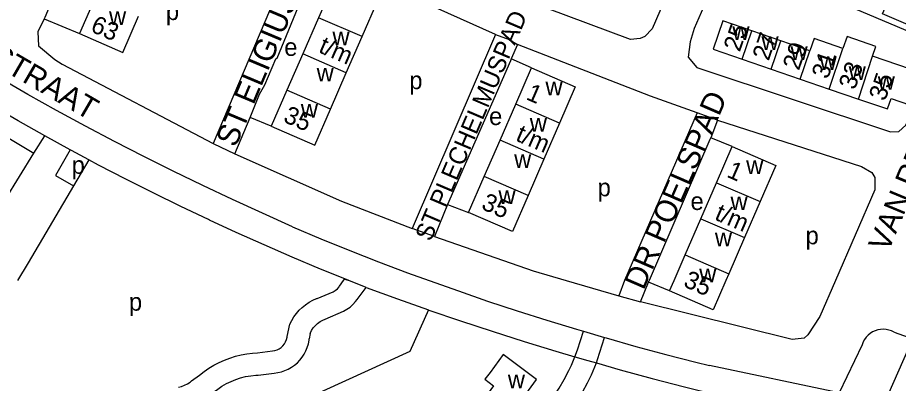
# Model space of a CAD drawing. Extents: x 162804 to 165059, y 381530 to 382901.
# Drawn here: x 163445.8 to 163644.1, y 381726.8 to 381809.3 of the extents above; entities that cross this region are included whole.
import ezdxf

# ---------------------------------------------------------------- set-up
doc = ezdxf.new("R2010")
doc.units = 0
for name, color, linetype in [('BLT_Basislijn', 7, 'Continuous'), ('BLT_Bebouwing', 7, 'Continuous'), ('BLT_Centroide', 7, 'Continuous'), ('BLT_Huisnummer', 7, 'Continuous'), ('BLT_Huisnummer_ tussenligend', 7, 'Continuous'), ('BLT_Huisnummer_reeks', 7, 'Continuous'), ('BLT_Onderverdeling_panden', 7, 'Continuous'), ('BLT_Straatnaam', 7, 'Continuous'), ('BLT_Straatnaam_verkleind', 7, 'Continuous')]:
    doc.layers.add(name, color=color, linetype=linetype)

msp = doc.modelspace()

# ---------------------------------------------------------------- linework, layer by layer
at = {"layer": 'BLT_Basislijn'}
for p, q in [((163508.81, 381825.69), (163489.79, 381780.91)), ((163553.38, 381805.49), (163514.14, 381823.1)), ((163653.55, 381803.05), (163629.47, 381813.33)), ((163451.76, 381809.01), (163459.7, 381805.68)), ((163553.38, 381805.49), (163534.59, 381761.76)), ((163558.32, 381803.23), (163556.95, 381800.02)), ((163561.46, 381797.95), (163556.95, 381800.02)), ((163494.7, 381778.56), (163498.12, 381786.73)), ((163502.88, 381784.79), (163498.12, 381786.73)), ((163598.78, 381787.81), (163582.41, 381750)), ((163603.38, 381786.16), (163598.78, 381787.81)), ((163603.38, 381786.16), (163601.85, 381782.2)), ((163449.46, 381778.72), (163451.88, 381782.63)), ((163457.64, 381779.46), (163451.88, 381782.63)), ((163489.79, 381780.91), (163494.7, 381778.56)), ((163606.68, 381780.21), (163601.85, 381782.2)), ((163461.83, 381777.22), (163458.38, 381771.38)), ((163458.38, 381771.38), (163448.14, 381754)), ((163542.58, 381767.18), (163539.63, 381759.95)), ((163542.58, 381767.18), (163547.34, 381765.32)), ((163539.63, 381759.95), (163534.59, 381761.76)), ((163448.14, 381754), (163445.78, 381750)), ((163518.26, 381748.73), (163519.19, 381750)), ((163519.19, 381750), (163519.4, 381750.29)), ((163519.4, 381750.29), (163520.19, 381750.08)), ((163520.37, 381750), (163520.19, 381750.08)), ((163524.27, 381748.46), (163520.37, 381750)), ((163569.3, 381750), (163581.13, 381746.53)), ((163582.41, 381750), (163581.13, 381746.53)), ((163586.04, 381745.22), (163587.85, 381749.62)), ((163587.85, 381749.62), (163588.01, 381750)), ((163592.58, 381747.66), (163587.85, 381749.62)), ((163513.21, 381746), (163516.81, 381747.48)), ((163522.25, 381745.71), (163524.27, 381748.46)), ((163581.13, 381746.53), (163586.04, 381745.22)), ((163515.04, 381741.34), (163519.18, 381743.08)), ((163506.48, 381737.41), (163507.08, 381740.19)), ((163511.62, 381738.11), (163511.45, 381736.89)), ((163573.17, 381738.57), (163577.92, 381737.18)), ((163643.14, 381738.37), (163647.37, 381736.86)), ((163638.42, 381716.6), (163647.37, 381736.86)), ((163499.77, 381733.71), (163503.15, 381734.15)), ((163570.52, 381730.95), (163571.26, 381732.83)), ((163575.02, 381728.75), (163576.09, 381731.43)), ((163499.97, 381728.71), (163503.55, 381729.17)), ((163484.97, 381727.38), (163486.71, 381728.67))]:
    msp.add_line(p, q, dxfattribs=at)
for points in [[(163597.55, 381827.29), (163588.69, 381806.75), (163587.02, 381805), (163585.93, 381804.58), (163583.75, 381804.36), (163564.87, 381811.42), (163541.46, 381821.29), (163539.68, 381823.17), (163539.55, 381824.83), (163549.28, 381848.27)], [(163465.65, 381841.88), (163451.89, 381809.28), (163451.76, 381809.01)], [(163605.48, 381823.75), (163598.15, 381806.85), (163597.24, 381803.85), (163596.76, 381800.38), (163598.72, 381798.05), (163642.29, 381783.55), (163644.18, 381783.63), (163645.81, 381785.02), (163653.55, 381803.05)], [(163498.12, 381786.73), (163500.21, 381791.99), (163501.43, 381794.13), (163503.96, 381800.02), (163504.25, 381800.16), (163512.11, 381819.35), (163512.27, 381819.65)], [(163507.64, 381762.13), (163500.89, 381765.16), (163494.16, 381768.26), (163487.47, 381771.43), (163480.82, 381774.68), (163474.2, 381777.99), (163467.62, 381781.38), (163461.07, 381784.84), (163454.57, 381788.37), (163448.1, 381791.97), (163441.67, 381795.64), (163435.28, 381799.37), (163428.93, 381803.18), (163422.62, 381807.06), (163418.08, 381809.9)], [(163451.76, 381809.01), (163450.36, 381806.05), (163450.49, 381802.91), (163454.18, 381799.86), (163455.82, 381798.75), (163489.79, 381780.91)], [(163553.38, 381805.49), (163556.45, 381804.34), (163558.32, 381803.23)], [(163598.78, 381787.81), (163588.32, 381791.54), (163558.32, 381803.23)], [(163556.95, 381800.02), (163556.73, 381799.52), (163542.58, 381767.18)], [(163436.05, 381791.78), (163433.78, 381788.09), (163449.46, 381778.72)], [(163451.88, 381782.63), (163445.87, 381786.02), (163439.9, 381789.49), (163436.05, 381791.78)], [(163603.38, 381786.16), (163635.76, 381775.75), (163638.15, 381774.36), (163638.79, 381773.24), (163638.82, 381770.47), (163629.96, 381750)], [(163588.01, 381750), (163588.05, 381750.11), (163601.73, 381781.89), (163601.85, 381782.2)], [(163439.13, 381770.55), (163442.96, 381768.22), (163449.46, 381778.72)], [(163457.64, 381779.46), (163454.34, 381773.65), (163458.38, 381771.38)], [(163461.83, 381777.22), (163457.93, 381779.3), (163457.64, 381779.46)], [(163489.01, 381763.62), (163488.73, 381763.75), (163482.5, 381766.72), (163476.3, 381769.76), (163470.14, 381772.87), (163464.02, 381776.05), (163461.83, 381777.22)], [(163494.7, 381778.56), (163518.73, 381767.87), (163534.59, 381761.76)], [(163520.19, 381750.08), (163513.98, 381752.6), (163507.62, 381755.28), (163501.29, 381758.03), (163494.99, 381760.85), (163489.01, 381763.62)], [(163507.64, 381762.13), (163514.08, 381759.43), (163520.56, 381756.81), (163527.06, 381754.26), (163533.59, 381751.78), (163538.44, 381750)], [(163539.63, 381759.95), (163561.84, 381752.19), (163569.3, 381750)], [(163538.44, 381750), (163545.02, 381747.66), (163551.62, 381745.39), (163558.26, 381743.19), (163564.91, 381741.08), (163571.59, 381739.04), (163573.17, 381738.57)], [(163629.96, 381750), (163626.43, 381741.93), (163623.72, 381737.77), (163622.86, 381737.06), (163620.22, 381736.76), (163586.04, 381745.22)], [(163516.81, 381747.48), (163517.32, 381747.8), (163517.78, 381748.18), (163518.18, 381748.62), (163518.26, 381748.73)], [(163524.27, 381748.46), (163531.32, 381745.87), (163538.27, 381743.42)], [(163507.08, 381740.19), (163507.51, 381741.04), (163508.01, 381741.84), (163508.58, 381742.61), (163509.21, 381743.32), (163509.89, 381743.97), (163510.63, 381744.57), (163511.42, 381745.1), (163512.25, 381745.56), (163513.11, 381745.96), (163513.21, 381746)], [(163519.18, 381743.08), (163519.93, 381743.53), (163520.63, 381744.04), (163521.28, 381744.62), (163521.88, 381745.25), (163522.25, 381745.71)], [(163538.27, 381743.42), (163534.12, 381734.01), (163500, 381718.5), (163478.02, 381708.51), (163453.55, 381693.34), (163440.16, 381684.96)], [(163538.27, 381743.42), (163538.4, 381743.37), (163545.51, 381740.93), (163552.65, 381738.58), (163559.81, 381736.3), (163566.99, 381734.1), (163571.26, 381732.83)], [(163511.62, 381738.11), (163511.96, 381738.74), (163512.35, 381739.32), (163512.82, 381739.86), (163513.34, 381740.34), (163513.91, 381740.76), (163514.52, 381741.11), (163515.04, 381741.34)], [(163643.14, 381738.37), (163642.57, 381738.65), (163641.97, 381738.85), (163641.35, 381738.98), (163640.72, 381739.02), (163640.09, 381738.99), (163639.47, 381738.88), (163638.87, 381738.69), (163638.29, 381738.42), (163637.76, 381738.09), (163637.27, 381737.68), (163636.84, 381737.23), (163636.46, 381736.72), (163636.16, 381736.16), (163635.91, 381735.54)], [(163503.15, 381734.15), (163503.68, 381734.24), (163504.2, 381734.4), (163504.68, 381734.63), (163505.13, 381734.94), (163505.52, 381735.3), (163505.86, 381735.73), (163506.13, 381736.19), (163506.33, 381736.69), (163506.45, 381737.22), (163506.48, 381737.41)], [(163571.26, 381732.83), (163571.87, 381734.37), (163573.17, 381738.57)], [(163576.09, 381731.43), (163576.38, 381732.18), (163577.92, 381737.18)], [(163577.92, 381737.18), (163578.29, 381737.07), (163585.02, 381735.18), (163591.76, 381733.37), (163598.53, 381731.64), (163601.59, 381730.89)], [(163503.55, 381729.17), (163504.38, 381729.28), (163505.18, 381729.46), (163505.97, 381729.72), (163506.73, 381730.06), (163507.46, 381730.47), (163508.14, 381730.95), (163508.77, 381731.48), (163509.35, 381732.08), (163509.87, 381732.73), (163510.32, 381733.43), (163510.7, 381734.17), (163511.01, 381734.94), (163511.25, 381735.73), (163511.41, 381736.55), (163511.45, 381736.89)], [(163635.91, 381735.54), (163630.75, 381724.69), (163601.59, 381730.89)], [(163486.71, 381728.67), (163487.75, 381729.49), (163488.83, 381730.24), (163489.96, 381730.92), (163491.13, 381731.53), (163492.33, 381732.07), (163493.56, 381732.54), (163494.82, 381732.93), (163496.1, 381733.25), (163497.39, 381733.48), (163498.7, 381733.64), (163499.77, 381733.71)], [(163571.26, 381732.83), (163574.19, 381731.97), (163576.09, 381731.43)], [(163576.09, 381731.43), (163581.42, 381729.92), (163588.67, 381727.95), (163595.94, 381726.05), (163603.23, 381724.23), (163604.56, 381723.92)], [(163562.45, 381718.4), (163563.86, 381720.17), (163565.2, 381721.99), (163566.48, 381723.86), (163567.69, 381725.77), (163568.83, 381727.72), (163569.9, 381729.71), (163570.52, 381730.95)], [(163481.99, 381725.98), (163482.69, 381726.16), (163483.37, 381726.4), (163484.01, 381726.72), (163484.62, 381727.11), (163484.97, 381727.38)], [(163489.92, 381724.84), (163490.83, 381725.55), (163491.79, 381726.19), (163492.79, 381726.77), (163493.83, 381727.28), (163494.9, 381727.71), (163496, 381728.07), (163497.12, 381728.35), (163498.26, 381728.56), (163499.41, 381728.68), (163499.97, 381728.71)], [(163566.31, 381715.22), (163567.77, 381717.06), (163569.17, 381718.95), (163570.5, 381720.88), (163571.77, 381722.86), (163572.96, 381724.88), (163574.09, 381726.93), (163575.02, 381728.75)]]:
    msp.add_lwpolyline(points, dxfattribs=at)
at = {"layer": 'BLT_Bebouwing'}
for p, q in [((163517.11, 381817.41), (163513.55, 381809.26)), ((163463.24, 381813.84), (163459.7, 381805.68)), ((163513.55, 381809.26), (163509.99, 381801.1)), ((163519.79, 381796.83), (163523.35, 381804.99)), ((163617.64, 381804.05), (163611.09, 381806.29)), ((163624.18, 381801.8), (163617.64, 381804.05)), ((163509.99, 381801.1), (163506.43, 381792.95)), ((163608.9, 381799.9), (163615.45, 381797.66)), ((163516.23, 381788.67), (163519.79, 381796.83)), ((163557.93, 381789.8), (163561.46, 381797.95)), ((163615.45, 381797.66), (163622, 381795.42)), ((163622, 381795.42), (163628.54, 381793.17)), ((163506.43, 381792.95), (163502.88, 381784.79)), ((163628.54, 381793.17), (163635.09, 381790.93)), ((163554.4, 381781.64), (163557.93, 381789.8)), ((163567.82, 381785.52), (163564.29, 381777.36)), ((163550.87, 381773.48), (163554.4, 381781.64)), ((163603.16, 381772.06), (163606.68, 381780.21)), ((163564.29, 381777.36), (163560.76, 381769.2)), ((163547.34, 381765.32), (163550.87, 381773.48)), ((163599.63, 381763.93), (163603.16, 381772.06)), ((163612.98, 381767.82), (163609.46, 381759.68)), ((163596.11, 381755.79), (163599.63, 381763.93)), ((163609.46, 381759.68), (163605.93, 381751.54)), ((163593.61, 381750), (163596.11, 381755.79)), ((163605.93, 381751.54), (163605.27, 381750)), ((163592.58, 381747.66), (163593.61, 381750))]:
    msp.add_line(p, q, dxfattribs=at)
for points in [[(163523.35, 381804.99), (163526.9, 381813.14), (163517.11, 381817.41)], [(163652.76, 381813.71), (163650.3, 381808.02), (163649.45, 381806.26), (163640.52, 381810.11), (163643.79, 381817.7), (163646.09, 381816.71)], [(163459.7, 381805.68), (163469.48, 381801.43), (163473.02, 381809.59)], [(163611.09, 381806.29), (163604.55, 381808.54), (163602.36, 381802.15), (163608.9, 381799.9)], [(163631.63, 381802.35), (163625.16, 381804.57), (163624.18, 381801.8)], [(163638.29, 381800.6), (163639.04, 381802.77), (163632.54, 381805.01), (163631.63, 381802.35)], [(163635.09, 381790.93), (163641.64, 381788.69), (163642.45, 381791.06), (163646.63, 381789.62), (163649.68, 381796.66), (163638.29, 381800.6)], [(163561.46, 381797.95), (163571.35, 381793.67), (163567.82, 381785.52)], [(163502.88, 381784.79), (163512.67, 381780.52), (163516.23, 381788.67)], [(163606.68, 381780.21), (163616.5, 381775.95), (163612.98, 381767.82)], [(163560.76, 381769.2), (163557.23, 381761.04), (163547.34, 381765.32)], [(163605.27, 381750), (163602.43, 381743.4), (163592.58, 381747.66)], [(163557.79, 381721.13), (163562.64, 381727.71), (163555.14, 381733.31), (163552.15, 381729.31), (163550.98, 381727.75), (163552.97, 381726.26), (163549.68, 381721.86), (163551.23, 381720.7), (163555.23, 381717.7), (163557.79, 381721.13)]]:
    msp.add_lwpolyline(points, dxfattribs=at)
at = {"layer": 'BLT_Onderverdeling_panden'}
for p, q in [((163523.35, 381804.99), (163513.55, 381809.26)), ((163608.9, 381799.9), (163611.09, 381806.29)), ((163615.45, 381797.66), (163617.64, 381804.05)), ((163519.79, 381796.83), (163509.99, 381801.1)), ((163622, 381795.42), (163624.18, 381801.8)), ((163628.54, 381793.17), (163631.63, 381802.35)), ((163635.09, 381790.93), (163638.29, 381800.6)), ((163516.23, 381788.67), (163506.43, 381792.95)), ((163567.82, 381785.52), (163557.93, 381789.8)), ((163564.29, 381777.36), (163554.4, 381781.64)), ((163560.76, 381769.2), (163550.87, 381773.48)), ((163603.16, 381772.06), (163612.98, 381767.82)), ((163599.63, 381763.93), (163609.46, 381759.68)), ((163596.11, 381755.79), (163605.93, 381751.54))]:
    msp.add_line(p, q, dxfattribs=at)

# ---------------------------------------------------------------- texts
at = {"layer": 'BLT_Centroide'}
for s, p in [('w', (163466.36, 381807.62)), ('p', (163479.17, 381808.73)), ('w', (163606.72, 381804.22)), ('w', (163516.67, 381803.03)), ('w', (163613.27, 381801.97)), ('e', (163505.82, 381800.64)), ('w', (163619.81, 381799.72)), ('w', (163626.36, 381797.5)), ('w', (163513.11, 381794.88)), ('w', (163632.91, 381795.25)), ('p', (163533.97, 381793.15)), ('w', (163564.64, 381791.75)), ('w', (163639.45, 381793)), ('w', (163509.55, 381786.72)), ('e', (163551.94, 381785.06)), ('w', (163561.11, 381783.56)), ('p', (163457.95, 381774.05)), ('w', (163557.58, 381775.41)), ('w', (163609.83, 381774)), ('p', (163576.37, 381769)), ('w', (163554.05, 381767.25)), ('e', (163597.3, 381765.91)), ('w', (163606.3, 381765.88)), ('w', (163602.78, 381757.75)), ('p', (163623.2, 381758.18)), ('w', (163599.26, 381749.59)), ('p', (163470.84, 381743.21)), ('w', (163556.16, 381725.75))]:
    msp.add_text(s, height=4, dxfattribs=at).set_placement(p)
at = {"layer": 'BLT_Huisnummer'}
for s, rotation, p in [('25', 71.0822, (163608.38, 381801.38)), ('29', 71.0875, (163621.7, 381797.21)), ('35', 71.074, (163641.11, 381790.3))]:
    msp.add_text(s, height=4, rotation=rotation, dxfattribs=at).set_placement(p)
at = {"layer": 'BLT_Huisnummer_ tussenligend'}
for s, rotation, p in [('27', 71.0822, (163614.88, 381799.37)), ('31', 71.0875, (163628.22, 381795.25)), ('33', 71.0875, (163634.31, 381792.83))]:
    msp.add_text(s, height=4, rotation=rotation, dxfattribs=at).set_placement(p)
at = {"layer": 'BLT_Huisnummer_reeks'}
for s, rotation, p in [('63', 336.5278, (163461.98, 381806.24)), ('t/m', 336.4348, (163513.32, 381801.55)), ('1', 336.5941, (163560.06, 381790.93)), ('35', 336.4348, (163505.38, 381785.88)), ('t/m', 336.5968, (163557.7, 381781.64)), ('1', 336.5941, (163605.24, 381773.45)), ('35', 336.5996, (163549.97, 381766.23)), ('t/m', 336.6208, (163602.5, 381763.84)), ('35', 336.5996, (163595.48, 381748.76))]:
    msp.add_text(s, height=4, rotation=rotation, dxfattribs=at).set_placement(p)
at = {"layer": 'BLT_Straatnaam'}
for s, height, rotation, p in [('GEERT GROOTESTRAAT', 5, 329.8331, (163392.63, 381826.32)), ('ST ELIGIUSPAD', 5, 67.1781, (163494.86, 381779.83)), ('VAN RENESSEWEG', 5, 67.4162, (163641.8, 381756.22)), ('DR POELSPAD', 4.9999, 66.5614, (163586.73, 381747.66))]:
    msp.add_text(s, height=height, rotation=rotation, dxfattribs=at).set_placement(p)
at = {"layer": 'BLT_Straatnaam_verkleind'}
msp.add_text('ST PLECHELMUSPAD', height=4, rotation=66.8957, dxfattribs=at).set_placement((163538.81, 381758.62))

doc.saveas('drawing.dxf')
